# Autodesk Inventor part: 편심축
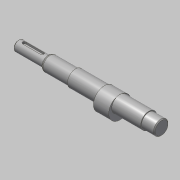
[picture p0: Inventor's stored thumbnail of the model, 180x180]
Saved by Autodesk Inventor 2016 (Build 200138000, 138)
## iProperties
Created: 2017-08
Part Number: 편심축
Material: 강철, 연강
Document SubType Name: Modeling
Designer: mduedu
Density: 1 g/cm^3
Appearance: 강철
Author: mduedu
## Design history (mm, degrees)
sketch "스케치1"
  geometry: L1 (0, 0)-(168, 0); L2 (168, 0)-(168, 8.5); L3 (168, 8.5)-(153, 8.5); L4 (153, 8.5)-(153, 9.5); L5 (153, 9.5)-(67, 9.5); L6 (67, 9.5)-(67, 8.5); L7 (67, 8.5)-(35, 8.5); L8 (35, 8.5)-(35, 6); L9 (35, 6)-(0, 6); L10 (0, 6)-(0, 0)
  constraints: 20 end point, 6 parallel, 2 collinear, 2 perpendicular, 1 horizontal
  dimensions: "d0" = 168 distance of L1.start L1.end; "d1" = 17 diameter of L3 L1; "d2" = 19 diameter of L5 L1; "d3" = 12 diameter of L9 L1; "d4" = 35 distance of L8.end L9.end; "d5" = 15 distance of L2.end L3.end; "d6" = 86 distance of L4.end L5.end
revolve "회전1" sketch "스케치1" stored, may be unused: angle "d7" = 90 deg
node "작업 평면1"
sketch "스케치2"
  geometry: C1 r 9.5 at (0, 0) reference; C2 r 13 at (0, -3.5); 1 further point
  constraints: 1 centre point, 1 tangent, 1 vertical alignment
  dimensions: "d8" = 3.5 distance of point (0, 0) C2.centre
extrude "돌출1" join sketch "스케치2" stored distance "d9" = 18; taper "d10" = 0 deg
chamfer "모따기1" distance "d11" = 1; stored, may be unused: second distance "d12" = 2, angle "d13" = 45 deg
node "작업 평면2"
sketch "스케치3"
  geometry: L1 (10.5, -2)-(-10.5, -2); L2 (-10.5, -2)-(-10.5, 2); L3 (-10.5, 2)-(10.5, 2); L4 (10.5, 2)-(10.5, -2); L5 (17.5, 6)-(17.5, -6) reference; L6 (-17.5, 8.5)-(-17.5, -8.5) reference; A1 r 2 centre (10.5, 0) between (10.5, -2) and (10.5, 2); A2 r 2 centre (-10.5, 0) between (-10.5, 2) and (-10.5, -2); A3 r 2 centre (10.5, 0) between (10.5, 2) and (10.5, -2); A4 r 2 centre (-10.5, 0) between (-10.5, -2) and (-10.5, 2); 1 further point
  constraints: 8 end point, 8 point on circle, 4 centre point, 2 midpoint, 2 parallel, 1 horizontal, 1 horizontal alignment, 1 perpendicular
  dimensions: "d14" = 25 dimension on A2 A1; "d16" = 4 distance between parallel lines of L3 L1; "d17" = 5 distance edge to line of A1 L5; "d46" = 5 distance edge to line of A2 L6 (derived)
extrude "돌출2" cut sketch "스케치3" distance "d18" = 2.5; taper "d19" = 0 deg
chamfer "모따기2" distance "d20" = 1; stored, may be unused: second distance "d21" = 2, angle "d22" = 45 deg
chamfer "모따기4" distance "d39" = 1.82; stored, may be unused: second distance "d40" = 2, angle "d41" = 30 deg
fillet "모깎기4" dims "d45" = 2
hole "구멍1" diameter "d29" = 3.242; stored, may be unused: countersink angle "d33" = 90 deg, drill point angle "d35" = 118 deg; dims "d30" = 8, "d31" = 4, "d32" = 2, "d34" = 10, "d36" = 10, "d37" = 10
node "솔리드1"
node "절단 모서리 투영1"
